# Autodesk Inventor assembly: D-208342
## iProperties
Created: 2007-10
Part Number: D-208342
Document SubType Name: Weldment
Designer: TH
Weld Material: Welded Steel Mild (Black-Flat)
Mass: 602.959 g
Surface Area: 279.565 cm^2
Volume: 76.8088 cm^3
Density: 7.85013 g/cm^3
Description: FRONT PIVOT WELDMENT
Component Category: Lower Component
Author: TH
